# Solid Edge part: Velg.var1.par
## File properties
Author: jaanm
Template: Ansi Metric part.par
Last saved by: jaanm
Revision: 11
Application: Solid Edge
Accuracy: 0,990
Face Style: Model Default
Coef. of Thermal Exp: 0.0
Thermal Conductivity: 0.0
Specific Heat: 0.0
Modulus of Elasticity: 0.0
Poisson's Ratio: 0.0
Yield Stress: 0.0
Ultimate Stress: 0.0
Elongation: 0.0
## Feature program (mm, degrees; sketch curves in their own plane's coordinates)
sketch for "unnamed RevolvedProtrusion 1" plane through (0, 0, 0) normal (0, -1, 0) x-axis (1, 0, 0)
  line (-83.955, 71.5) -> (66.045, 71.5)
  arc centre (91.045, 65.875) radius 25.625 from (91.045, 91.5) to (66.045, 71.5) ccw
  line (91.045, 68.8049) -> (91.045, 91.5)
  arc centre (67.0995, 68.8049) radius 23.9455 from (91.045, 68.8049) to (74.7362, 46.1098) cw
  line (-35.7904, 46.1098) -> (74.7362, 46.1098)
  arc centre (-35.7904, 22.6241) radius 23.4857 from (-58.9938, 18.9939) to (-35.7904, 46.1098) cw
  line (-58.9938, -33.5) -> (-58.9938, 18.9939)
  line (-108.955, -33.5) -> (-58.9938, -33.5)
  line (-108.955, 91.5) -> (-108.955, -33.5)
  arc centre (-108.955, 65.875) radius 25.625 from (-108.955, 91.5) to (-83.955, 71.5) cw
revolve "unnamed RevolvedProtrusion 1" add finite 360 deg
sketch for "unnamed Cutout 1" plane through (-108.955, 0, -33.5) normal (-1, 0, 0) x-axis (0, -1, 0)
  circle centre (0, 0) radius 15
extrude "unnamed Cutout 1" cut to key point along -normal
sketch for "v__" plane through (-108.955, 0, -33.5) normal (-1, 0, 0) x-axis (0, 0, -1)
  hole centre (-30, 0) bore radius 6.5
hole "v__" through  CounterBoreDepth = 8.75 mm
pattern "Pattern_1" of "v__" along a curve  XDirCount = 7; XDirSpacing = 13.464 mm
hole "unnamed Hole 1" through
hole "unnamed Hole 2" through
hole "unnamed Hole 3" through
hole "unnamed Hole 4" through
hole "unnamed Hole 5" through
hole "unnamed Hole 6" through
sketch for "unnamed Cutout 2" plane through (-108.955, 0, -33.5) normal (-1, 0, 0) x-axis (0, 0, -1)
  line (-42.697, 13.8731) -> (-75.7135, 24.6008)
  line (-42.697, -13.8731) -> (-75.7135, -24.6008)
extrude "unnamed Cutout 2" cut to key point along -normal
pattern "Pattern_2" of "unnamed Cutout 2" along a curve  XDirCount = 5; XDirSpacing = 18.8496 mm
extrude "unnamed Cutout 3" cut finite 73.1647
extrude "unnamed Cutout 4" cut finite 73.1647
extrude "unnamed Cutout 5" cut finite 73.1647
extrude "unnamed Cutout 6" cut finite 73.1647
sketch for "ExtrudedCutout_8" #1 plane through (-108.955, 0, -33.5) normal (-1, 0, 0) x-axis (0, 1, 0)
  circle centre (0, 0) radius 44.8943
sketch for "ExtrudedCutout_8" #2 plane through (-108.955, 0, -33.5) normal (-1, 0, 0) x-axis (0, 1, 0)
  circle centre (0, 0) radius 112.5
extrude "ExtrudedCutout_8" cut finite 5 along -normal
fillet "Round_1" radius 6
fillet "Round_2" radius 10
pattern "Pattern_3" of "Round_2" along a curve  XDirCount = 5; XDirSpacing = 18.8496 mm
fillet "unnamed Round 1"
fillet "unnamed Round 2"
fillet "unnamed Round 3"
fillet "unnamed Round 4"
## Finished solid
Body 1: solid body, 77 faces, 180 edges, 89 vertices.
  Faces by surface: cylinder 40, plane 24, torus 12, cone 1
  Edges by curve: circle 81, line 68, intersection 30, curve on surface 1
Bounding box of the edges (mm; curved faces can reach further): 200.000 x 250.000 x 250.000, from (-108.955, -125, -158.5) to (91.045, 125, 91.5).
Cylindrical faces by radius (mm): R6.5 x7, R10 x17, R15 x1, R44.8943 x9, R79.6098 x5, R105 x1
Conical faces (half-angle, radius in mm at the cone's reference point): 0 deg R79.6098 x1
Toroidal faces (ring radius, tube radius in mm): R56.1241 r23.4857 x3, R89.6098 r10 x5, R99.375 r25.625 x2, R102.3049 r23.9455 x1, R106.5839 r6 x1
Planar faces by outward normal: +x 2, +z 2, -x 12, oblique 8
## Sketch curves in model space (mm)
circle centre (-108.955, 0, -33.5) radius 112.5
circle centre (-108.955, 0, -33.5) radius 44.8943
line (-108.955, 0, 11.3943) -> (-108.955, 0, 11.3197)
arc centre (-108.955, 0, -33.5) radius 79.6098 from (-108.955, 24.6008, 42.2135) through (-108.955, 0, 46.1098) to (-108.955, -24.6008, 42.2135)
line (-108.955, 13.8731, 9.197) -> (-108.955, 24.6008, 42.2135)
arc centre (-108.955, 0, -33.5) radius 44.8943 from (-108.955, 13.8731, 9.197) through (-108.955, 0, 11.3943) to (-108.955, -13.8731, 9.197)
line (-108.955, -13.8731, 9.197) -> (-108.955, -24.6008, 42.2135)
circle centre (-108.955, 0, -33.5) radius 15
line (-8.955, 0, -33.5) -> (108.955, 0, -33.5)
line (-83.955, 0, 71.5) -> (66.045, 0, 71.5)
arc centre (91.045, 0, 65.875) radius 25.625 from (91.045, 0, 91.5) through (74.4571, 0, 85.4066) to (66.045, 0, 71.5)
line (91.045, 0, 68.8049) -> (91.045, 0, 91.5)
arc centre (67.0995, 0, 68.8049) radius 23.9455 from (91.045, 0, 68.8049) through (86.1218, 0, 54.2606) to (74.7362, 0, 46.1098)
line (-35.7904, 0, 46.1098) -> (74.7362, 0, 46.1098)
arc centre (-35.7904, 0, 22.6241) radius 23.4857 from (-58.9938, 0, 18.9939) through (-53.1724, 0, 38.4179) to (-35.7904, 0, 46.1098)
line (-58.9938, 0, -33.5) -> (-58.9938, 0, 18.9939)
line (-108.955, 0, -33.5) -> (-58.9938, 0, -33.5)
line (-108.955, 0, 91.5) -> (-108.955, 0, -33.5)
arc centre (-108.955, 0, 65.875) radius 25.625 from (-108.955, 0, 91.5) through (-92.3672, 0, 85.4066) to (-83.955, 0, 71.5)
line (-83.955, 0, 71.5) -> (-83.9948, 0, 71.5)
line (-83.9948, 0, 71.5) -> (-83.955, 0, 71.5)
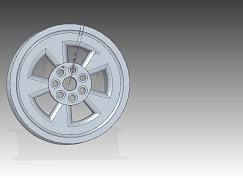
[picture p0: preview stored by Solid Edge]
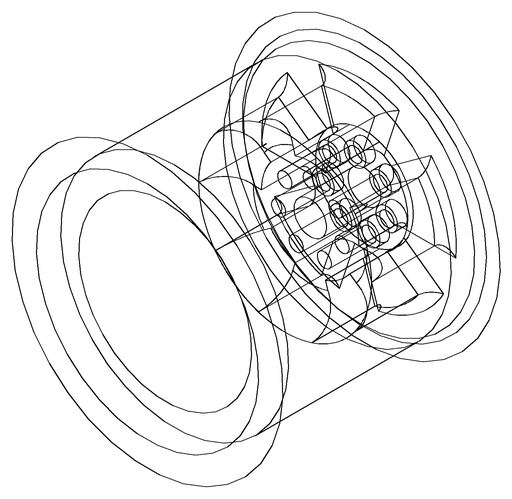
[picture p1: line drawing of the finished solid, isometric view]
